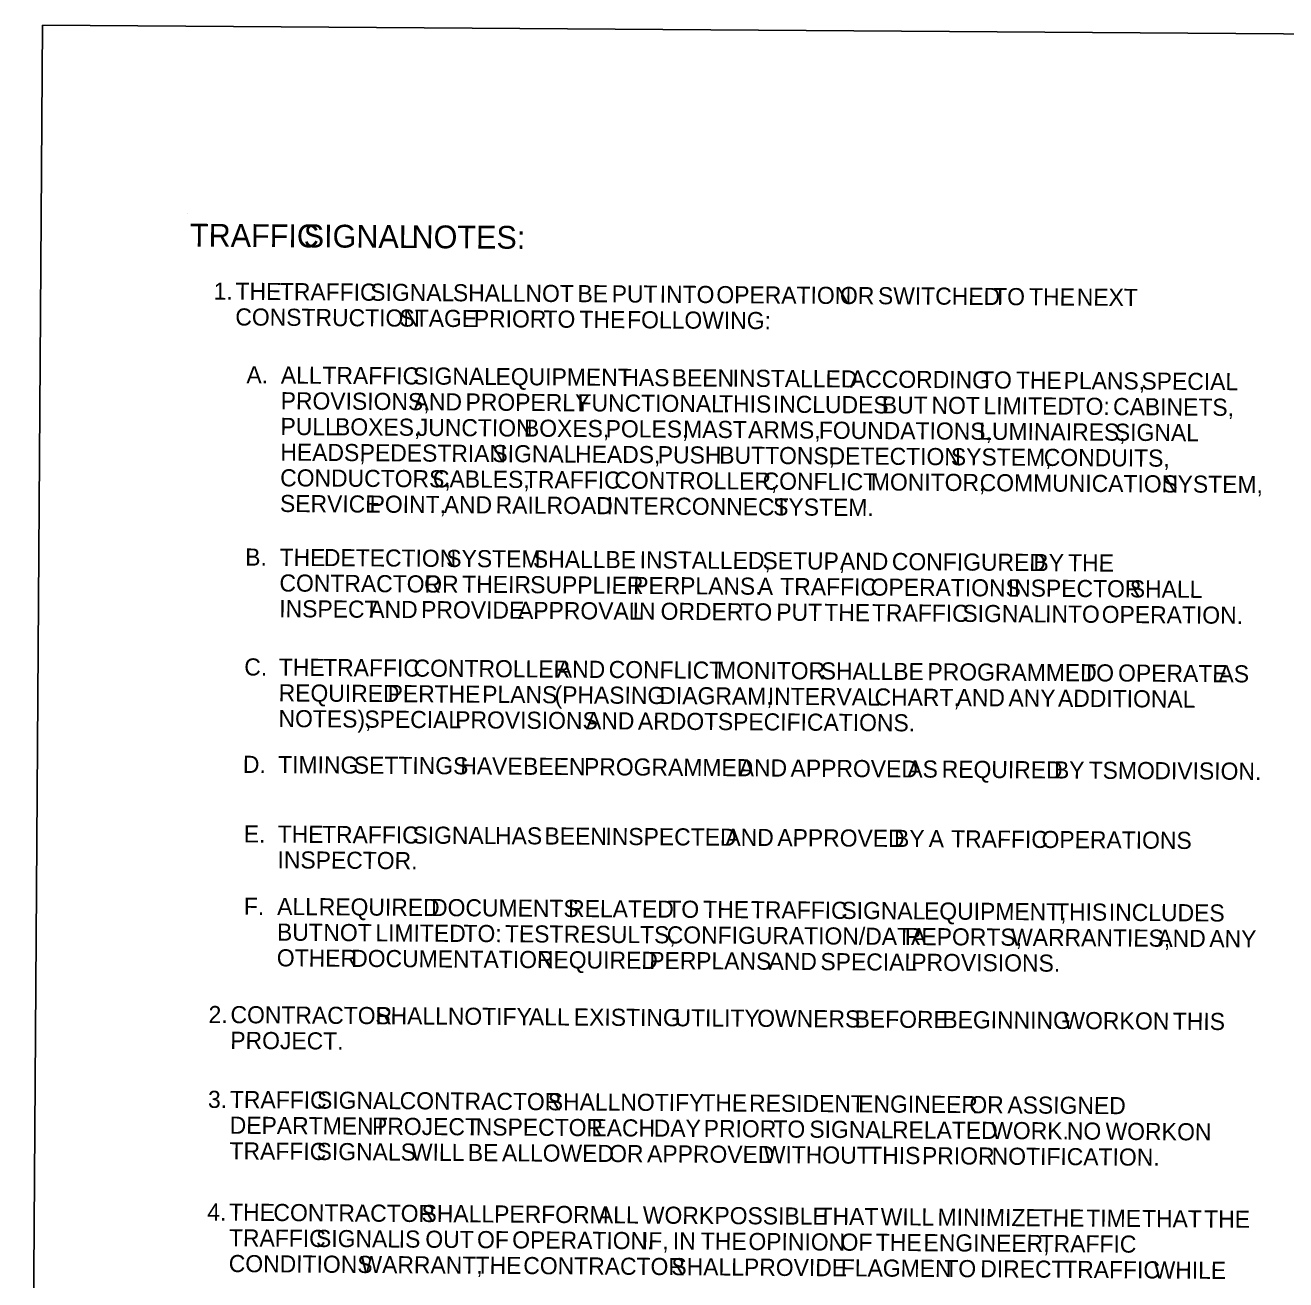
# Model space of a CAD drawing. Extents: x 1802516 to 1809813, y 570772 to 574149.
# Drawn here: x 1808996.4 to 1809261.3, y 571506.8 to 571770.6 of the extents above; entities that cross this region are included whole.
import ezdxf

# ---------------------------------------------------------------- set-up
doc = ezdxf.new("R2010")
doc.units = 0
for name, color, linetype in [('Default', 7, 'Continuous'), ('MOD_COR', 7, 'Continuous'), ('MOD_COR_Point Control', 7, 'Continuous')]:
    doc.layers.add(name, color=color, linetype=linetype)

msp = doc.modelspace()

# ---------------------------------------------------------------- linework, layer by layer
at = {"layer": 'Default'}
msp.add_line((1809030.47, 571730.99), (1809030.47, 571730.99), dxfattribs=at)
at = {"layer": 'MOD_COR'}
msp.add_lwpolyline([(1808996.39, 571245.59), (1809808.87, 571239.95), (1809812.51, 571764.94), (1809000.03, 571770.58)], close=True, dxfattribs=at)

# ---------------------------------------------------------------- texts
at = {"layer": 'MOD_COR_Point Control'}
for s, height, p in [('TRAFFIC', 4.8, (1809031, 571724.04)), (' SIGNAL', 4.8, (1809053.13, 571723.89)), (' NOTES:', 4.8, (1809075.79, 571723.73)), ('1.', 3.6, (1809035.97, 571712.88)), ('THE', 3.6, (1809040.58, 571712.85)), (' TRAFFIC', 3.6, (1809048.56, 571712.79)), (' SIGNAL', 3.6, (1809067.56, 571712.66)), (' SHALL', 3.6, (1809084.93, 571712.54)), (' NOT', 3.6, (1809100.18, 571712.43)), (' BE', 3.6, (1809111.11, 571712.36)), (' PUT', 3.6, (1809118.3, 571712.31)), (' INTO', 3.6, (1809128.39, 571712.24)), (' OPERATION', 3.6, (1809140.3, 571712.15)), (' OR', 3.6, (1809166.28, 571711.97)), (' SWITCHED', 3.6, (1809174.26, 571711.92)), (' TO', 3.6, (1809198.47, 571711.75)), (' THE', 3.6, (1809206.02, 571711.7)), (' NEXT', 3.6, (1809216.04, 571711.63)), ('CONSTRUCTION', 3.6, (1809040.54, 571707.45)), (' STAGE', 3.6, (1809073.69, 571707.22)), (' PRIOR', 3.6, (1809089.32, 571707.11)), (' TO', 3.6, (1809103.97, 571707.01)), (' THE', 3.6, (1809111.53, 571706.95)), (' FOLLOWING:', 3.6, (1809121.54, 571706.88)), ('A.', 3.6, (1809042.88, 571695.28)), ('ALL', 3.6, (1809050.11, 571695.23)), (' TRAFFIC', 3.6, (1809057.51, 571695.18)), (' SIGNAL', 3.6, (1809076.52, 571695.05)), (' EQUIPMENT', 3.6, (1809093.89, 571694.93)), (' HAS', 3.6, (1809120.54, 571694.74)), (' BEEN', 3.6, (1809130.91, 571694.67)), (' INSTALLED', 3.6, (1809143.72, 571694.58)), (' ACCORDING', 3.6, (1809168.38, 571694.41)), (' TO', 3.6, (1809195.71, 571694.22)), (' THE', 3.6, (1809203.26, 571694.17)), (' PLANS,', 3.6, (1809213.28, 571694.1)), (' SPECIAL', 3.6, (1809229.63, 571693.98)), ('PROVISIONS,', 3.6, (1809050.07, 571689.83)), (' AND', 3.6, (1809076.67, 571689.65)), (' PROPERLY', 3.6, (1809087.58, 571689.57)), (' FUNCTIONAL.', 3.6, (1809111.12, 571689.41)), (' THIS', 3.6, (1809140.87, 571689.2)), (' INCLUDES', 3.6, (1809152.16, 571689.12)), (' BUT', 3.6, (1809175.07, 571688.96)), (' NOT', 3.6, (1809185.51, 571688.89)), (' LIMITED', 3.6, (1809196.44, 571688.81)), (' TO:', 3.6, (1809214.96, 571688.69)), (' CABINETS,', 3.6, (1809223.67, 571688.62)), ('PULL', 3.6, (1809050.03, 571684.43)), (' BOXES,', 3.6, (1809060.16, 571684.36)), (' JUNCTION', 3.6, (1809077.34, 571684.24)), (' BOXES,', 3.6, (1809099.86, 571684.08)), (' POLES,', 3.6, (1809117.03, 571683.97)), (' MAST', 3.6, (1809133.33, 571683.85)), (' ARMS,', 3.6, (1809146.96, 571683.76)), (' FOUNDATIONS,', 3.6, (1809161.84, 571683.65)), (' LUMINAIRES,', 3.6, (1809195.54, 571683.42)), (' SIGNAL', 3.6, (1809224.06, 571683.22)), ('HEADS,', 3.6, (1809050, 571679.03)), (' PEDESTRIAN', 3.6, (1809065.33, 571678.92)), (' SIGNAL', 3.6, (1809093.23, 571678.73)), (' HEADS,', 3.6, (1809110.61, 571678.61)), (' PUSH', 3.6, (1809127.98, 571678.49)), (' BUTTONS,', 3.6, (1809140.9, 571678.4)), (' DETECTION', 3.6, (1809163.87, 571678.24)), (' SYSTEM,', 3.6, (1809189.59, 571678.06)), (' CONDUITS,', 3.6, (1809209.11, 571677.93)), ('CONDUCTORS,', 3.6, (1809049.96, 571673.63)), (' CABLES,', 3.6, (1809080.73, 571673.42)), (' TRAFFIC', 3.6, (1809099.86, 571673.28)), (' CONTROLLER,', 3.6, (1809118.86, 571673.15)), (' CONFLICT', 3.6, (1809150.02, 571672.94)), (' MONITOR,', 3.6, (1809172.77, 571672.78)), (' COMMUNICATION', 3.6, (1809195.64, 571672.62)), (' SYSTEM,', 3.6, (1809234.03, 571672.35)), ('SERVICE', 3.6, (1809049.92, 571668.23)), (' POINT,', 3.6, (1809067.42, 571668.11)), (' AND', 3.6, (1809083, 571668)), (' RAILROAD', 3.6, (1809093.91, 571667.93)), (' INTERCONNECT', 3.6, (1809117.22, 571667.76)), (' SYSTEM.', 3.6, (1809152.24, 571667.52)), ('B.', 3.6, (1809042.61, 571656.96)), ('THE', 3.6, (1809049.84, 571656.91)), (' DETECTION', 3.6, (1809057.82, 571656.86)), (' SYSTEM', 3.6, (1809083.54, 571656.68)), (' SHALL', 3.6, (1809101.75, 571656.55)), (' BE', 3.6, (1809116.99, 571656.45)), (' INSTALLED,', 3.6, (1809124.18, 571656.4)), (' SETUP,', 3.6, (1809149.99, 571656.22)), (' AND', 3.6, (1809166.27, 571656.11)), (' CONFIGURED', 3.6, (1809177.18, 571656.03)), (' BY', 3.6, (1809206.94, 571655.82)), (' THE', 3.6, (1809214.22, 571655.77)), ('CONTRACTOR', 3.6, (1809049.81, 571651.51)), (' OR', 3.6, (1809078.9, 571651.31)), (' THEIR', 3.6, (1809086.89, 571651.26)), (' SUPPLIER', 3.6, (1809101.16, 571651.16)), (' PER', 3.6, (1809122.83, 571651.01)), (' PLANS.', 3.6, (1809132.68, 571650.94)), (' A', 3.6, (1809149, 571650.82)), (' TRAFFIC', 3.6, (1809153.72, 571650.79)), (' OPERATIONS', 3.6, (1809172.73, 571650.66)), (' INSPECTOR', 3.6, (1809201.54, 571650.46)), (' SHALL', 3.6, (1809227.19, 571650.28)), ('INSPECT', 3.6, (1809049.77, 571646.11)), (' AND', 3.6, (1809067.35, 571645.99)), (' PROVIDE', 3.6, (1809078.25, 571645.92)), (' APPROVAL', 3.6, (1809098.61, 571645.77)), (' IN', 3.6, (1809122.69, 571645.61)), (' ORDER', 3.6, (1809128.58, 571645.57)), (' TO', 3.6, (1809145.34, 571645.45)), (' PUT', 3.6, (1809152.89, 571645.4)), (' THE', 3.6, (1809162.98, 571645.33)), (' TRAFFIC', 3.6, (1809173, 571645.26)), (' SIGNAL', 3.6, (1809192, 571645.13)), (' INTO', 3.6, (1809209.38, 571645.01)), (' OPERATION.', 3.6, (1809221.29, 571644.92)), ('C.', 3.6, (1809042.42, 571633.86)), ('THE', 3.6, (1809049.68, 571633.81)), (' TRAFFIC', 3.6, (1809057.66, 571633.75)), (' CONTROLLER', 3.6, (1809076.66, 571633.62)), (' AND', 3.6, (1809106.77, 571633.41)), (' CONFLICT', 3.6, (1809117.67, 571633.33)), (' MONITOR', 3.6, (1809140.42, 571633.18)), (' SHALL', 3.6, (1809162.23, 571633.03)), (' BE', 3.6, (1809177.48, 571632.92)), (' PROGRAMMED', 3.6, (1809184.66, 571632.87)), (' TO', 3.6, (1809217.18, 571632.64)), (' OPERATE', 3.6, (1809224.73, 571632.59)), (' AS', 3.6, (1809245.83, 571632.44)), ('REQUIRED', 3.6, (1809049.64, 571628.41)), (' PER', 3.6, (1809071.21, 571628.26)), (' THE', 3.6, (1809081.07, 571628.19)), (' PLANS', 3.6, (1809091.08, 571628.12)), (' (PHASING', 3.6, (1809106.29, 571628.01)), (' DIAGRAM,', 3.6, (1809128.32, 571627.86)), (' INTERVAL', 3.6, (1809151.1, 571627.7)), (' CHART,', 3.6, (1809173.54, 571627.55)), (' AND', 3.6, (1809190.78, 571627.43)), (' ANY', 3.6, (1809201.68, 571627.35)), (' ADDITIONAL', 3.6, (1809212.09, 571627.28)), ('NOTES),', 3.6, (1809049.61, 571623.01)), (' SPECIAL', 3.6, (1809066.32, 571622.89)), (' PROVISIONS', 3.6, (1809085.41, 571622.76)), (' AND', 3.6, (1809112.91, 571622.57)), (' ARDOT', 3.6, (1809123.82, 571622.49)), (' SPECIFICATIONS.', 3.6, (1809140.61, 571622.38)), ('D.', 3.6, (1809042.13, 571613.38)), ('TIMING', 3.6, (1809049.54, 571613.33)), (' SETTINGS', 3.6, (1809064.1, 571613.23)), (' HAVE', 3.6, (1809086.48, 571613.08)), (' BEEN', 3.6, (1809099.67, 571612.98)), (' PROGRAMMED', 3.6, (1809112.48, 571612.9)), (' AND', 3.6, (1809145, 571612.67)), (' APPROVED', 3.6, (1809155.9, 571612.59)), (' AS', 3.6, (1809180.43, 571612.42)), (' REQUIRED', 3.6, (1809187.66, 571612.37)), (' BY', 3.6, (1809211.26, 571612.21)), (' TSMO', 3.6, (1809218.54, 571612.16)), (' DIVISION.', 3.6, (1809232.36, 571612.06)), ('E.', 3.6, (1809042.32, 571598.76)), ('THE', 3.6, (1809049.44, 571598.71)), (' TRAFFIC', 3.6, (1809057.42, 571598.65)), (' SIGNAL', 3.6, (1809076.42, 571598.52)), (' HAS', 3.6, (1809093.79, 571598.4)), (' BEEN', 3.6, (1809104.17, 571598.33)), (' INSPECTED', 3.6, (1809116.98, 571598.24)), (' AND', 3.6, (1809142.2, 571598.06)), (' APPROVED', 3.6, (1809153.11, 571597.99)), (' BY', 3.6, (1809177.64, 571597.82)), (' A', 3.6, (1809184.92, 571597.77)), (' TRAFFIC', 3.6, (1809189.64, 571597.73)), (' OPERATIONS', 3.6, (1809208.64, 571597.6)), ('INSPECTOR.', 3.6, (1809049.4, 571593.31)), ('F.', 3.6, (1809042.33, 571583.55)), ('ALL', 3.6, (1809049.33, 571583.5)), (' REQUIRED', 3.6, (1809056.73, 571583.45)), (' DOCUMENTS', 3.6, (1809080.34, 571583.28)), (' RELATED', 3.6, (1809109.14, 571583.08)), (' TO', 3.6, (1809129.99, 571582.94)), (' THE', 3.6, (1809137.54, 571582.89)), (' TRAFFIC', 3.6, (1809147.56, 571582.82)), (' SIGNAL', 3.6, (1809166.57, 571582.68)), (' EQUIPMENT,', 3.6, (1809183.94, 571582.56)), (' THIS', 3.6, (1809211.48, 571582.37)), (' INCLUDES', 3.6, (1809222.78, 571582.29)), ('BUT', 3.6, (1809049.3, 571578.1)), (' NOT', 3.6, (1809057.7, 571578.04)), (' LIMITED', 3.6, (1809068.63, 571577.96)), (' TO:', 3.6, (1809087.15, 571577.84)), (' TEST', 3.6, (1809095.86, 571577.77)), (' RESULTS,', 3.6, (1809108.22, 571577.69)), (' CONFIGURATION/DATA', 3.6, (1809129.87, 571577.54)), (' REPORTS,', 3.6, (1809179.92, 571577.19)), (' WARRANTIES,', 3.6, (1809202.25, 571577.04)), (' AND', 3.6, (1809232.99, 571576.82)), (' ANY', 3.6, (1809243.9, 571576.75)), ('OTHER', 3.6, (1809049.26, 571572.7)), (' DOCUMENTATION', 3.6, (1809063.55, 571572.6)), (' REQUIRED', 3.6, (1809102.59, 571572.33)), (' PER', 3.6, (1809126.2, 571572.16)), (' PLANS', 3.6, (1809136.06, 571572.1)), (' AND', 3.6, (1809151.26, 571571.99)), (' SPECIAL', 3.6, (1809162.17, 571571.91)), (' PROVISIONS.', 3.6, (1809181.26, 571571.78)), ('2.', 3.6, (1809034.91, 571560.78)), ('CONTRACTOR', 3.6, (1809039.52, 571560.75)), (' SHALL', 3.6, (1809068.62, 571560.55)), (' NOTIFY', 3.6, (1809083.86, 571560.44)), (' ALL', 3.6, (1809100.9, 571560.32)), (' EXISTING', 3.6, (1809110.34, 571560.26)), (' UTILITY', 3.6, (1809131.49, 571560.11)), (' OWNERS', 3.6, (1809148.88, 571559.99)), (' BEFORE', 3.6, (1809169.35, 571559.85)), (' BEGINNING', 3.6, (1809187.79, 571559.72)), (' WORK', 3.6, (1809213.24, 571559.54)), (' ON', 3.6, (1809228.28, 571559.44)), (' THIS', 3.6, (1809236.23, 571559.38)), ('PROJECT.', 3.6, (1809039.48, 571555.35)), ('3.', 3.6, (1809034.79, 571542.94)), ('TRAFFIC', 3.6, (1809039.4, 571542.91)), (' SIGNAL', 3.6, (1809056.37, 571542.79)), (' CONTRACTOR', 3.6, (1809073.74, 571542.67)), (' SHALL', 3.6, (1809104.87, 571542.45)), (' NOTIFY', 3.6, (1809120.12, 571542.35)), (' THE', 3.6, (1809137.15, 571542.23)), (' RESIDENT', 3.6, (1809147.17, 571542.16)), (' ENGINEER', 3.6, (1809170.11, 571542)), (' OR', 3.6, (1809193.47, 571541.84)), (' ASSIGNED', 3.6, (1809201.46, 571541.78)), ('DEPARTMENT', 3.6, (1809039.36, 571537.51)), (' PROJECT', 3.6, (1809067.93, 571537.31)), (' INSPECTOR', 3.6, (1809088.39, 571537.17)), (' EACH', 3.6, (1809114.04, 571536.99)), (' DAY', 3.6, (1809127.14, 571536.9)), (' PRIOR', 3.6, (1809137.64, 571536.83)), (' TO', 3.6, (1809152.29, 571536.72)), (' SIGNAL', 3.6, (1809159.84, 571536.67)), (' RELATED', 3.6, (1809177.21, 571536.55)), (' WORK.', 3.6, (1809198.07, 571536.41)), (' NO', 3.6, (1809213.96, 571536.3)), (' WORK', 3.6, (1809222.09, 571536.24)), (' ON', 3.6, (1809237.13, 571536.14)), ('TRAFFIC', 3.6, (1809039.32, 571532.11)), (' SIGNALS', 3.6, (1809056.29, 571531.99)), (' WILL', 3.6, (1809076.11, 571531.85)), (' BE', 3.6, (1809088.06, 571531.77)), (' ALLOWED', 3.6, (1809095.24, 571531.72)), (' OR', 3.6, (1809117.76, 571531.56)), (' APPROVED', 3.6, (1809125.74, 571531.51)), (' WITHOUT', 3.6, (1809150.27, 571531.34)), (' THIS', 3.6, (1809172.21, 571531.19)), (' PRIOR', 3.6, (1809183.51, 571531.11)), (' NOTIFICATION.', 3.6, (1809198.16, 571531.01)), ('4.', 3.6, (1809034.63, 571519.25)), ('THE', 3.6, (1809039.23, 571519.22)), (' CONTRACTOR', 3.6, (1809047.21, 571519.16)), (' SHALL', 3.6, (1809078.34, 571518.95)), (' PERFORM', 3.6, (1809093.59, 571518.84)), (' ALL', 3.6, (1809115.41, 571518.69)), (' WORK', 3.6, (1809124.85, 571518.62)), (' POSSIBLE', 3.6, (1809139.89, 571518.52)), (' THAT', 3.6, (1809161.77, 571518.37)), (' WILL', 3.6, (1809174.84, 571518.27)), (' MINIMIZE', 3.6, (1809186.79, 571518.19)), (' THE', 3.6, (1809208.03, 571518.04)), (' TIME', 3.6, (1809218.04, 571517.97)), (' THAT', 3.6, (1809229.76, 571517.89)), (' THE', 3.6, (1809242.83, 571517.8)), ('TRAFFIC', 3.6, (1809039.2, 571513.82)), (' SIGNAL', 3.6, (1809056.16, 571513.7)), (' IS', 3.6, (1809073.54, 571513.58)), (' OUT', 3.6, (1809079.13, 571513.54)), (' OF', 3.6, (1809090, 571513.46)), (' OPERATION.', 3.6, (1809097.39, 571513.41)), (' IF,', 3.6, (1809124.65, 571513.22)), (' IN', 3.6, (1809131.14, 571513.18)), (' THE', 3.6, (1809137.03, 571513.14)), (' OPINION', 3.6, (1809147.04, 571513.07)), (' OF', 3.6, (1809166.41, 571512.93)), (' THE', 3.6, (1809173.81, 571512.88)), (' ENGINEER,', 3.6, (1809183.83, 571512.81)), (' TRAFFIC', 3.6, (1809208.24, 571512.64)), ('CONDITIONS', 3.6, (1809039.16, 571508.42)), (' WARRANT,', 3.6, (1809065.5, 571508.23)), (' THE', 3.6, (1809089.7, 571508.07)), (' CONTRACTOR', 3.6, (1809099.72, 571508)), (' SHALL', 3.6, (1809130.85, 571507.78)), (' PROVIDE', 3.6, (1809146.1, 571507.67)), (' FLAGMEN', 3.6, (1809166.45, 571507.53)), (' TO', 3.6, (1809188.21, 571507.38)), (' DIRECT', 3.6, (1809195.76, 571507.33)), (' TRAFFIC', 3.6, (1809213.19, 571507.21)), (' WHILE', 3.6, (1809232.2, 571507.08))]:
    msp.add_text(s, height=height, rotation=359.6021, dxfattribs=at).set_placement(p)

doc.saveas('drawing.dxf')
